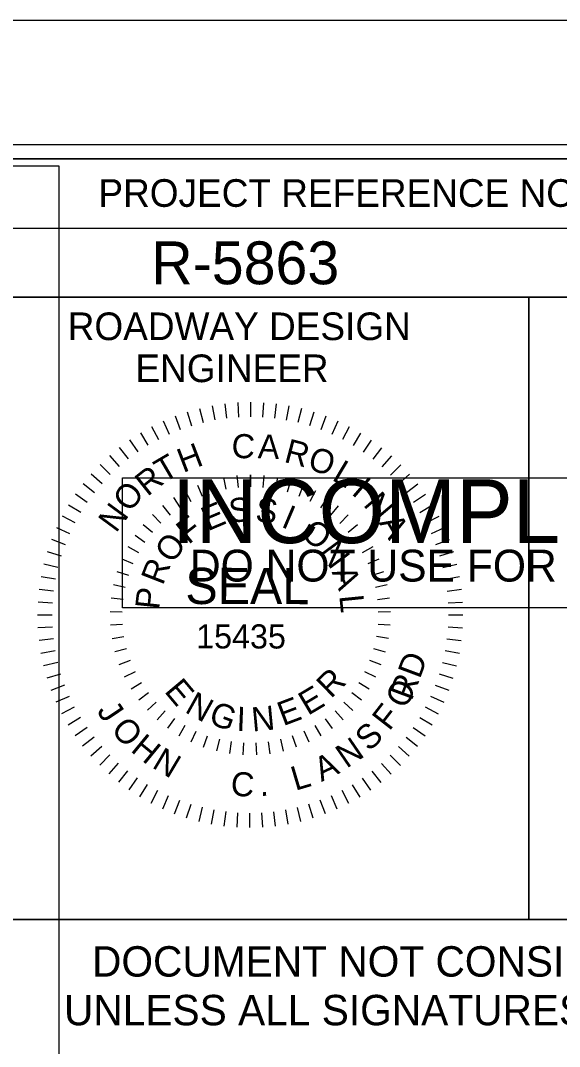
# Model space of a CAD drawing. Extents: x 557032 to 558716, y 525869 to 526969.
# Drawn here: x 558507.5 to 558605, y 526783.7 to 526969.2 of the extents above; entities that cross this region are included whole.
import ezdxf

# ---------------------------------------------------------------- set-up
doc = ezdxf.new("R2010")
doc.units = 0
for name, color, linetype in [('Old_Level_21', 7, 'Continuous'), ('Scratch_Level_5', 7, 'Continuous'), ('Sheet Cutting Line CELL', 7, 'Continuous'), ('Sheet Data Field CELL', 7, 'Continuous'), ('Sheet Plot Border Inside CELL', 7, 'Continuous'), ('Sheet Plot Border Outside CELL', 7, 'Continuous'), ('Sheet Profile CELL', 7, 'Continuous'), ('Sheet Profile Grid Major CELL', 7, 'Continuous'), ('Sheet Sticker Exception Certification CELL', 7, 'Continuous'), ('Sheet Sticker Incomplete CELL', 7, 'Continuous')]:
    doc.layers.add(name, color=color, linetype=linetype)

msp = doc.modelspace()

# ---------------------------------------------------------------- linework, layer by layer
at = {"layer": 'Old_Level_21'}
for p, q in [((558537.68, 526898.46), (558538.46, 526895.95)), ((558539.93, 526899.08), (558540.55, 526896.53)), ((558542.2, 526899.57), (558542.67, 526896.99)), ((558544.49, 526899.91), (558544.8, 526897.31)), ((558546.81, 526900.12), (558546.96, 526897.5)), ((558549.13, 526900.18), (558549.13, 526897.56)), ((558551.45, 526900.11), (558551.29, 526897.49)), ((558553.77, 526899.9), (558553.45, 526897.3)), ((558556.06, 526899.55), (558555.59, 526896.97)), ((558558.33, 526899.06), (558557.7, 526896.51)), ((558560.57, 526898.43), (558559.79, 526895.92)), ((558533.34, 526896.82), (558534.41, 526894.43)), ((558535.49, 526897.71), (558536.42, 526895.25)), ((558562.76, 526897.67), (558561.83, 526895.22)), ((558564.91, 526896.77), (558563.83, 526894.38)), ((558531.25, 526895.81), (558532.47, 526893.48)), ((558566.99, 526895.76), (558565.77, 526893.43)), ((558527.27, 526893.41), (558528.76, 526891.25)), ((558529.23, 526894.67), (558530.58, 526892.42)), ((558569.02, 526894.61), (558567.66, 526892.37)), ((558570.97, 526893.35), (558569.47, 526891.19)), ((558525.4, 526892.03), (558527.02, 526889.97)), ((558572.83, 526891.97), (558571.22, 526889.91)), ((558523.62, 526890.55), (558525.35, 526888.58)), ((558574.62, 526890.48), (558572.88, 526888.52)), ((558521.92, 526888.96), (558523.77, 526887.1)), ((558576.31, 526888.88), (558574.45, 526887.03)), ((558518.84, 526885.48), (558520.9, 526883.87)), ((558520.33, 526887.27), (558522.29, 526885.53)), ((558541.86, 526886.03), (558542.48, 526883.93)), ((558544.24, 526886.61), (558544.66, 526884.46)), ((558546.66, 526886.96), (558546.87, 526884.79)), ((558549.11, 526887.07), (558549.11, 526884.89)), ((558549.11, 526884.89), (558549.11, 526887.07)), ((558551.56, 526886.95), (558551.35, 526884.78)), ((558553.98, 526886.59), (558553.56, 526884.45)), ((558556.36, 526886.01), (558555.73, 526883.91)), ((558577.9, 526887.19), (558575.93, 526885.45)), ((558517.46, 526883.62), (558519.61, 526882.13)), ((558537.33, 526884.19), (558538.34, 526882.25)), ((558539.55, 526885.22), (558540.37, 526883.19)), ((558558.67, 526885.19), (558557.84, 526883.17)), ((558560.89, 526884.15), (558559.87, 526882.22)), ((558579.38, 526885.4), (558577.32, 526883.79)), ((558535.22, 526882.95), (558536.41, 526881.12)), ((558563, 526882.91), (558561.8, 526881.08)), ((558580.75, 526883.53), (558578.6, 526882.04)), ((558516.19, 526881.67), (558518.43, 526880.31)), ((558531.4, 526879.89), (558532.92, 526878.32)), ((558533.23, 526881.51), (558534.6, 526879.8)), ((558564.98, 526881.47), (558563.6, 526879.76)), ((558582.01, 526881.58), (558579.77, 526880.22)), ((558515.05, 526879.65), (558517.37, 526878.43)), ((558529.73, 526878.1), (558531.39, 526876.69)), ((558566.8, 526879.84), (558565.28, 526878.28)), ((558568.47, 526878.05), (558566.8, 526876.64)), ((558583.15, 526879.55), (558580.83, 526878.34)), ((558514.03, 526877.56), (558516.42, 526876.48)), ((558584.16, 526877.46), (558581.77, 526876.39)), ((558513.14, 526875.42), (558515.59, 526874.48)), ((558528.24, 526876.16), (558530.03, 526874.91)), ((558569.96, 526876.1), (558568.16, 526874.86)), ((558585.05, 526875.31), (558582.6, 526874.39)), ((558512.38, 526873.22), (558514.88, 526872.44)), ((558526.94, 526874.08), (558528.85, 526873.01)), ((558571.24, 526874.02), (558569.33, 526872.95)), ((558585.81, 526873.12), (558583.3, 526872.34)), ((558511.75, 526870.98), (558514.29, 526870.36)), ((558525.85, 526871.88), (558527.86, 526871.01)), ((558572.33, 526871.82), (558570.32, 526870.95)), ((558586.43, 526870.88), (558583.88, 526870.26)), ((558524.98, 526869.59), (558527.06, 526868.92)), ((558573.19, 526869.53), (558571.11, 526868.86)), ((558511.26, 526868.71), (558513.84, 526868.24)), ((558524.34, 526867.23), (558526.47, 526866.76)), ((558573.83, 526867.16), (558571.7, 526866.7)), ((558586.91, 526868.61), (558584.33, 526868.14)), ((558510.91, 526866.42), (558513.51, 526866.1)), ((558587.26, 526866.31), (558584.66, 526866)), ((558510.7, 526864.11), (558513.31, 526863.94)), ((558523.92, 526864.82), (558526.09, 526864.56)), ((558574.24, 526864.75), (558572.07, 526864.49)), ((558587.46, 526864), (558584.85, 526863.85)), ((558510.62, 526861.78), (558513.24, 526861.78)), ((558523.74, 526862.38), (558525.92, 526862.32)), ((558574.42, 526862.31), (558572.23, 526862.25)), ((558587.53, 526861.68), (558584.91, 526861.68)), ((558510.69, 526859.46), (558513.3, 526859.61)), ((558523.79, 526859.93), (558525.97, 526860.08)), ((558574.35, 526859.86), (558572.18, 526860.02)), ((558587.46, 526859.35), (558584.84, 526859.51)), ((558524.09, 526857.5), (558526.24, 526857.86)), ((558571.91, 526857.87), (558574.07, 526857.51)), ((558510.9, 526857.15), (558513.5, 526857.46)), ((558587.24, 526857.04), (558584.64, 526857.36)), ((558511.24, 526854.85), (558513.82, 526855.32)), ((558524.61, 526855.1), (558526.72, 526855.67)), ((558573.52, 526855.03), (558571.42, 526855.61)), ((558586.89, 526854.74), (558584.32, 526855.22)), ((558511.72, 526852.58), (558514.27, 526853.2)), ((558525.37, 526852.77), (558527.41, 526853.54)), ((558572.76, 526852.71), (558570.72, 526853.48)), ((558586.4, 526852.48), (558583.86, 526853.1)), ((558512.34, 526850.34), (558514.85, 526851.11)), ((558526.34, 526850.53), (558528.3, 526851.5)), ((558571.78, 526850.47), (558569.82, 526851.44)), ((558585.78, 526850.23), (558583.27, 526851.02)), ((558513.1, 526848.14), (558515.55, 526849.07)), ((558527.53, 526848.39), (558529.39, 526849.53)), ((558570.59, 526848.33), (558568.73, 526849.48)), ((558585.02, 526848.04), (558582.56, 526848.98)), ((558513.99, 526846), (558516.38, 526847.07)), ((558528.92, 526846.37), (558530.66, 526847.69)), ((558569.2, 526846.31), (558567.46, 526847.64)), ((558584.12, 526845.9), (558581.73, 526846.97)), ((558515, 526843.91), (558517.32, 526845.12)), ((558530.49, 526844.5), (558532.09, 526845.98)), ((558567.61, 526844.44), (558566.02, 526845.93)), ((558583.1, 526843.81), (558580.78, 526845.03)), ((558516.14, 526841.88), (558518.38, 526843.23)), ((558532.24, 526842.78), (558533.69, 526844.42)), ((558534.15, 526841.25), (558535.44, 526843.01)), ((558563.95, 526841.2), (558562.66, 526842.97)), ((558565.86, 526842.74), (558564.41, 526844.37)), ((558581.96, 526841.79), (558579.72, 526843.15)), ((558517.4, 526839.93), (558519.56, 526841.41)), ((558536.2, 526839.9), (558537.31, 526841.78)), ((558561.9, 526839.87), (558560.79, 526841.75)), ((558580.69, 526839.84), (558578.54, 526841.33)), ((558518.77, 526838.06), (558520.84, 526839.67)), ((558538.37, 526838.76), (558539.29, 526840.74)), ((558540.63, 526837.83), (558541.36, 526839.89)), ((558543.49, 526839.25), (558542.96, 526837.13)), ((558555.11, 526837.11), (558554.59, 526839.24)), ((558557.45, 526837.81), (558556.73, 526839.87)), ((558559.72, 526838.73), (558558.81, 526840.71)), ((558579.32, 526837.97), (558577.25, 526839.59)), ((558520.26, 526836.27), (558522.22, 526838)), ((558545.38, 526836.66), (558545.7, 526838.82)), ((558547.82, 526836.41), (558547.92, 526838.6)), ((558550.26, 526836.41), (558550.17, 526838.59)), ((558552.7, 526836.64), (558552.39, 526838.81)), ((558577.82, 526836.19), (558575.87, 526837.93)), ((558521.85, 526834.58), (558523.7, 526836.43)), ((558576.23, 526834.5), (558574.38, 526836.35)), ((558523.54, 526832.98), (558525.28, 526834.94)), ((558525.32, 526831.49), (558526.94, 526833.55)), ((558572.75, 526831.42), (558571.14, 526833.49)), ((558574.54, 526832.91), (558572.8, 526834.87)), ((558527.19, 526830.11), (558528.68, 526832.26)), ((558570.88, 526830.05), (558569.39, 526832.21)), ((558529.13, 526828.85), (558530.5, 526831.09)), ((558531.16, 526827.7), (558532.38, 526830.02)), ((558566.9, 526827.65), (558565.68, 526829.98)), ((558568.93, 526828.79), (558567.57, 526831.04)), ((558533.25, 526826.69), (558534.32, 526829.07)), ((558535.39, 526825.79), (558536.33, 526828.24)), ((558562.66, 526825.75), (558561.73, 526828.21)), ((558564.81, 526826.64), (558563.74, 526829.03)), ((558537.58, 526825.03), (558538.37, 526827.53)), ((558539.82, 526824.4), (558540.45, 526826.95)), ((558542.09, 526823.91), (558542.57, 526826.49)), ((558544.39, 526823.56), (558544.71, 526826.16)), ((558553.66, 526823.55), (558553.35, 526826.15)), ((558555.96, 526823.89), (558555.49, 526826.47)), ((558558.23, 526824.38), (558557.61, 526826.92)), ((558560.47, 526825), (558559.69, 526827.5)), ((558546.7, 526823.35), (558546.86, 526825.96)), ((558549.02, 526823.27), (558549.03, 526825.89)), ((558551.35, 526823.34), (558551.19, 526825.96))]:
    msp.add_line(p, q, dxfattribs=at)
at = {"layer": 'Scratch_Level_5'}
msp.add_lwpolyline([(557999.45, 526942.96), (558514.45, 526942.96), (558514.5, 526442.96), (557999.5, 526442.96)], close=True, dxfattribs=at)
at = {"layer": 'Sheet Cutting Line CELL'}
msp.add_line((558716.45, 526969.22), (557032.45, 526969.22), dxfattribs=at)
at = {"layer": 'Sheet Plot Border Inside CELL'}
msp.add_lwpolyline([(557045.45, 525891.67), (558711.95, 525891.67), (558711.95, 526946.77), (557045.45, 526946.77)], close=True, dxfattribs=at)
at = {"layer": 'Sheet Plot Border Outside CELL'}
msp.add_lwpolyline([(557032.45, 525869.22), (558716.45, 525869.22), (558716.45, 526969.22), (557032.45, 526969.22)], close=True, dxfattribs=at)
at = {"layer": 'Sheet Profile CELL'}
for p, q in [((558499.4, 526931.67), (558699.45, 526931.67)), ((558599.45, 526919.17), (558599.45, 526806.72))]:
    msp.add_line(p, q, dxfattribs=at)
for points in [[(558699.45, 526944.22), (557199.45, 526944.22), (557199.45, 525894.22), (558699.45, 525894.22)], [(558499.4, 526944.22), (558699.45, 526944.22), (558699.45, 526919.17), (558499.4, 526919.17)], [(558499.4, 526919.17), (558599.45, 526919.17), (558599.45, 526806.67), (558499.4, 526806.67)], [(558599.45, 526919.17), (558699.45, 526919.17), (558699.45, 526806.67), (558599.45, 526806.67)]]:
    msp.add_lwpolyline(points, close=True, dxfattribs=at)
at = {"layer": 'Sheet Profile Grid Major CELL'}
msp.add_lwpolyline([(558299.45, 526944.22), (558349.45, 526944.22), (558349.45, 526444.22), (558399.45, 526444.22), (558399.45, 526944.22), (558449.45, 526944.22), (558449.45, 526444.22), (558499.45, 526444.22), (558499.45, 526944.22), (558525.75, 526944.22)], dxfattribs=at)
at = {"layer": 'Sheet Sticker Exception Certification CELL'}
msp.add_line((558499.4, 526806.67), (558699.44, 526806.67), dxfattribs=at)
msp.add_line((558499.4, 526806.67), (558699.44, 526806.67), dxfattribs=at)
at = {"layer": 'Sheet Sticker Incomplete CELL'}
msp.add_lwpolyline([(558525.97, 526863.02), (558525.97, 526886.52), (558672.97, 526886.52), (558672.97, 526863.02)], close=True, dxfattribs=at)

# ---------------------------------------------------------------- texts
at = {"layer": 'Old_Level_21'}
for s, height, rotation, p in [('C', 4.36, 357.2771, (558545.62, 526890.18)), ('A', 4.36, 357.2771, (558550.39, 526890.09)), ('R', 4.36, 345.2678, (558555.02, 526889.44)), ('H', 4.36, 20.9878, (558536.93, 526887.39)), ('O', 4.36, 342.211, (558559.25, 526888.17)), ('T', 4.36, 30.4198, (558533.42, 526885.49)), ('L', 4.36, 329.0747, (558563.68, 526886.22)), ('R', 4.36, 38.5807, (558530.48, 526883.05)), ('O', 4.36, 51.6375, (558527.31, 526880.12)), ('I', 4.36, 319.4993, (558567.2, 526883.68)), ('N', 4.36, 310.2048, (558569.38, 526881.62)), ('N', 4.36, 53.5969, (558524.8, 526876.43)), ('E', 4.36, 22.8645, (558541.4, 526876.84)), ('S', 4.36, 7.5683, (558545.5, 526878.33)), ('S', 4.36, 352.272, (558549.86, 526878.69)), ('I', 4.36, 336.9758, (558554.5, 526877.74)), ('F', 4.36, 38.1608, (558537.9, 526874.37)), ('O', 4.36, 321.6795, (558558.02, 526876.03)), ('A', 4.36, 300.4373, (558572.26, 526878.4)), ('O', 4.36, 53.457, (558534.99, 526870.86)), ('N', 4.36, 306.3833, (558561.37, 526873.11)), ('R', 4.36, 68.7533, (558533.26, 526866.94)), ('SEAL', 6.553, 359.9202, (558537.34, 526863.71)), ('A', 4.36, 291.0871, (558563.76, 526869.53)), ('P', 4.36, 84.0495, (558532.59, 526862.61)), ('L', 4.36, 275.7908, (558565.17, 526865.2)), ('15435', 4.365, 359.9202, (558539.29, 526855.68)), (' RD', 4.365, 69.5926, (558577.7, 526844.57)), ('E', 4.36, 309.9903, (558533.41, 526847.89)), ('R', 4.36, 44.4851, (558563.68, 526846.5)), ('E', 4.36, 30.714, (558559.51, 526843.46)), ('O ', 4.365, 60.9198, (558577.07, 526844.55)), ('N', 4.36, 330.8453, (558537.07, 526844.24)), ('E', 4.36, 20.7281, (558555.03, 526841.6)), ('J', 4.36, 303.8552, (558521.23, 526844.34)), ('G', 4.36, 339.6116, (558541.34, 526842.19)), ('I', 4.36, 357.7064, (558546.54, 526840.79)), ('N', 4.36, 5.336, (558549.5, 526840.64)), ('F', 4.36, 52.1272, (558574.22, 526840.61)), ('O', 4.36, 311.927, (558523.72, 526840.86)), ('S', 4.36, 43.2446, (558570.58, 526836.91)), ('H', 4.36, 320.5697, (558527.28, 526837.17)), ('N', 4.36, 34.362, (558566.49, 526833.89)), ('N', 4.36, 329.2423, (558531.14, 526834.22)), ('A', 4.36, 25.5393, (558561.95, 526831.52)), ('L', 4.36, 16.5368, (558557.23, 526829.92)), ('C', 4.36, 356.0101, (558545.45, 526829.09)), ('.', 4.36, 3.7525, (558550.88, 526828.97))]:
    msp.add_text(s, height=height, rotation=rotation, dxfattribs=at).set_placement(p)
at = {"layer": 'Sheet Data Field CELL'}
msp.add_text('R-5863   ', height=7.75, dxfattribs=at).set_placement((558531.18, 526921.53))
at = {"layer": 'Sheet Profile CELL'}
for s, height, p in [('PROJECT REFERENCE NO.', 5.0001, (558521.62, 526935.53)), ('ROADWAY DESIGN', 5.0001, (558516.07, 526911.43)), ('ENGINEER', 5, (558528.32, 526903.83))]:
    msp.add_text(s, height=height, dxfattribs=at).set_placement(p)
at = {"layer": 'Sheet Sticker Exception Certification CELL'}
for s, p in [('DOCUMENT NOT CONSIDERED FINAL', (558520.47, 526796.33)), ('DOCUMENT NOT CONSIDERED FINAL', (558520.47, 526796.33)), ('UNLESS ALL SIGNATURES COMPLETED', (558515.4, 526787.53)), ('UNLESS ALL SIGNATURES COMPLETED', (558515.4, 526787.53))]:
    msp.add_text(s, height=5.5, dxfattribs=at).set_placement(p)
at = {"layer": 'Sheet Sticker Incomplete CELL'}
for s, height, p in [('INCOMPLETE PLANS', 11.52, (558534.92, 526874.72)), ('DO NOT USE FOR R/W ACQUISITION', 5.76, (558538.17, 526867.77))]:
    msp.add_text(s, height=height, dxfattribs=at).set_placement(p)

doc.saveas('drawing.dxf')
